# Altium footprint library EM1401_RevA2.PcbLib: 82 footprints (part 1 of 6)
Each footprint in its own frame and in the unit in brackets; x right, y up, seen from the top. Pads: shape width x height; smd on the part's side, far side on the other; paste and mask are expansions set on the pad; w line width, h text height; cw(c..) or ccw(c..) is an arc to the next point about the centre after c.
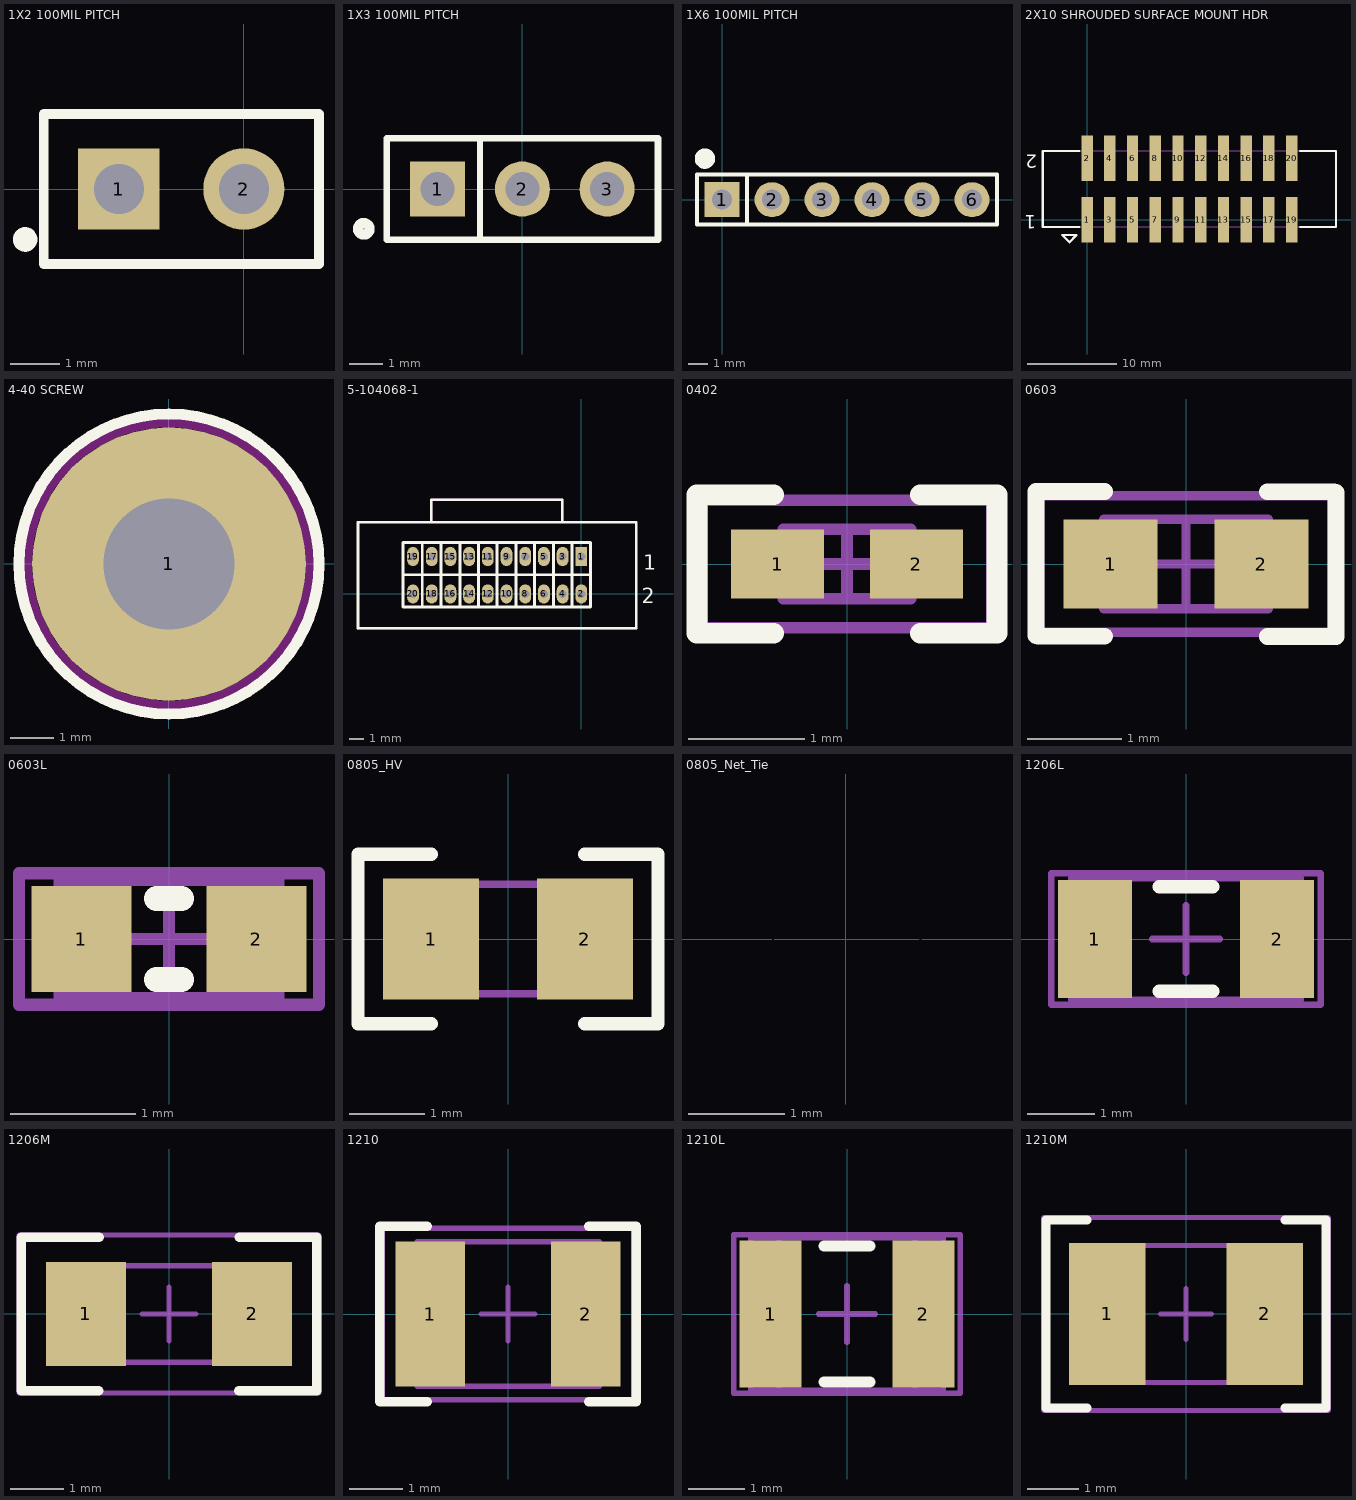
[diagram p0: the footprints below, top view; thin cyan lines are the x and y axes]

## 1X2 100MIL PITCH [mm] "100 mil 1x2 header, 230 mil above insulator"
height 8.382
pads (2):
  rect 1.65x1.65 hole 1.016: 1(-2.54,0)
  round 1.65 hole 1.016: 2(0,0)
Top Overlay:
  circle w0.25: c-4.441,-1.025 r0.125
  lines w0.2: -4.064,-1.524 1.525,-1.524 1.525,1.524 -4.064,1.524 -4.064,-1.524
Mechanical 5:
  text ".designator" at -0.875,-0.538 h1.02

## 1X3 100MIL PITCH [mm] "100 mil 1x3 header, 230 mil above insulator"
height 8.382
pads (3):
  rect 1.65x1.65 hole 1.016: 1(-2.54,0)
  round 1.65 hole 1.016: 2(0,0) 3(2.54,0)
Top Overlay:
  circle w0.305: c-4.754,-1.194 r0.173
  lines w0.178: -1.27,-1.524 -1.27,1.46
  lines w0.2: -4.064,-1.524 4.064,-1.524 4.064,1.524 -4.064,1.524 -4.064,-1.524
Mechanical 5:
  text ".designator" at -0.875,-0.538 h1.02
3D body: height 8.38, standoff -2.54, extent -3.81,-1.27 3.81,1.27

## 1X6 100MIL PITCH [mil] "CONN HEADER VERT SGL 6POS"
height 570
pads (6):
  rect 70x70 hole 40: 1(0,0)
  round 70 hole 40: 2(100,0) 3(200,0) 4(300,0) 5(400,0) 6(500,0)
Top Overlay:
  circle w20: c-34,82 r10.44
  lines w7.87: 50.2,-50 50.2,50 ; -50,-50 -50,50 550,50 550,-50 -50,-50
Mechanical 5:
  text ".Designator" at -0.94,-0.32 h40
Mechanical 13:
  lines w3.94: -50,-50 -50,50 550,50 550,-50 -50,-50
Mechanical 15:
  lines w3.94: -19.68,0 19.68,0 ; 0,-19.68 0,19.68 ; -50,-50 -50,50 550,50 550,-50 -50,-50
3D body: height 68.9, standoff 0, extent -50,-50 550,50

## 2X10 SHROUDED SURFACE MOUNT HDR [mil] "2X10 Shrouded Surface Mount HDR"
height 390.16
pads (20):
  rect 50x200 smd: 1(0,0) 2(0,270) 3(100,0) 4(100,270) 5(200,0) 6(200,270) 7(300,0) 8(300,270) 9(400,0) 10(400,270) 11(500,0) 12(500,270) 13(600,0) 14(600,270) 15(700,0) 16(700,270) 17(800,0) 18(800,270) 19(900,0) 20(900,270)
Top Overlay:
  lines w9.84: -109.24,-67.54 -46.24,-67.54 -77.74,-99.04 -109.24,-67.54
  lines w10: -35,-32.11 -195.85,-32.11 -195.85,302.54 -35,302.54 ; 937.11,-32.11 1095.49,-32.11 1095.49,302.54 937.46,302.54
  text "2" at -220,285 h60
  text "1" at -225,20 h60
Mechanical 15:
  lines w3.94: -195.85,-32.11 1095.49,-32.11 1095.49,302.54 -195.85,302.54 -195.85,-32.11
3D body: height 68.9, standoff 0, extent -194.67,-32.11 1095.49,302.54
3D body: height 349.4, standoff -130.6, extent -200,-46.5 1100,326.5

## 4-40 SCREW [mil] "Hole and Pad for 4-40 screw mount"
pads (1):
  round 250 hole 120: 1(0,0)
Top Overlay:
  circle w10: c0,0 r137
Keep-Out Layer:
  circle w10: c-0.36,0 r129.66

## 5-104068-1 [mm] "AMP 20PIN VERT HEADER ASSY"
height 8.89
pads (20):
  rect 0.8x1.3 hole 0.559: 1(0,2.54)
  oval 0.8x1.3 hole 0.559: 2(0,0) 3(-1.27,2.54) 4(-1.27,0) 5(-2.54,2.54) 6(-2.54,0) 7(-3.81,2.54) 8(-3.81,0) 9(-5.08,2.54) 10(-5.08,0) 11(-6.35,2.54) 12(-6.35,0) 13(-7.62,2.54) 14(-7.62,0) 15(-8.89,2.54) 16(-8.89,0) 17(-10.16,2.54) 18(-10.16,0) 19(-11.43,2.54) 20(-11.43,0)
Top Overlay:
  lines w0.178: -10.18,4.876 -10.18,6.4 -1.29,6.4 -1.29,4.876 ; -15.164,-2.337 3.734,-2.337 3.734,4.877 -15.164,4.877 -15.164,-2.337
  lines w0.2: -12.1,1.3 -10.8,1.3 -9.5,1.3 -8.2,1.3 ; -9.5,-0.9 -8.25,-0.9 -8.25,3.5 -9.5,3.5 ; -8.275,-0.9 -6.975,-0.9 -6.975,3.5 -8.275,3.5 ; -8.275,1.3 -6.975,1.3 ; -7.025,-0.9 -5.725,-0.9 -5.725,3.5 -7.025,3.5 ; -7.025,1.3 -5.725,1.3 ; -5.75,-0.9 -4.45,-0.9 -4.45,3.5 -5.75,3.5 ; -5.75,1.3 -4.45,1.3 ; -4.475,-0.9 -3.175,-0.9 -3.175,3.5 -4.475,3.5 ; -4.475,1.3 -3.175,1.3 ; -3.2,-0.9 -1.9,-0.9 -1.9,3.5 -3.2,3.5 ; -3.2,1.3 -1.9,1.3 ; -1.925,-0.9 -0.625,-0.9 -0.625,3.5 -1.925,3.5 ; -1.925,1.3 -0.625,1.3 ; -0.675,-0.9 0.625,-0.9 0.625,3.5 -0.675,3.5 ; -0.675,1.3 0.625,1.3 ; -12.1,3.5 -10.8,3.5 ; -12.1,3.5 -12.1,3.5 ; -12.1,3.5 -12.1,-0.9 -10.8,-0.9 ; -10.8,-0.9 -10.8,3.5 ; -10.8,-0.9 -9.525,-0.9 -9.525,3.5 -10.8,3.5
  text "1" at 4.191,1.651 h1.02
  text "2" at 4.115,-0.635 h1.02
Mechanical 5:
  text ".Designator" at -6.94,1.02 h1.02
Mechanical 15:
  lines w0.127: -10.18,4.876 -10.18,6.4 -1.29,6.4 -1.29,4.876 ; 3.734,-2.337 3.734,4.877 -15.164,4.877 -15.164,-2.337 3.759,-2.337
3D body: height 11.43, standoff -1.02, extent -15.164,-2.337 3.734,6.401

## 0402 [mm] "0402 from SM-752 data"
height 0.6
pads (2):
  rect 0.8x0.6 smd: 1(-0.6,0) 2(0.6,0)
Top Overlay:
  lines w0.178: -0.635,-0.597 -1.295,-0.597 -1.295,0.597 -0.635,0.597 ; 0.635,-0.597 1.295,-0.597 1.295,0.597 0.635,0.597
Mechanical 5:
  text ".Designator" at -1.117,-0.305 h0.61
Mechanical 13:
  lines w0.1: -0.35,-0.3 -0.35,0.3 ; 0.35,-0.3 0.35,0.3 ; -0.55,-0.3 -0.55,0.3 0.55,0.3 0.55,-0.3 -0.55,-0.3
Mechanical 15:
  lines w0.1: -0.3,0 0.3,0 ; 0,-0.3 0,0.3 ; -1.25,-0.55 -1.25,0.55 1.25,0.55 1.25,-0.55 -1.25,-0.55
3D body: height 0.6, standoff 0, extent -0.549,-0.299 -0.351,0.299
3D body: height 0.6, standoff 0, extent -0.349,-0.299 0.349,0.299
3D body: height 0.6, standoff 0, extent 0.351,-0.299 0.549,0.299

## 0603 [mm] "0603 from SM-752 data"
height 0.85
pads (2):
  rect 1x0.95 smd: 1(-0.8,0) 2(0.8,0)
Top Overlay:
  lines w0.178: -1.593,-0.762 -1.593,0.769 -0.864,0.769 ; -1.575,-0.767 -0.864,-0.767 ; 0.864,-0.769 1.593,-0.769 1.593,0.762 ; 0.864,0.767 1.575,0.767
Mechanical 5:
  text ".Designator" at -1.397,-0.381 h0.76
Mechanical 13:
  lines w0.1: -0.55,-0.475 -0.55,0.475 ; 0.55,-0.475 0.55,0.475 ; -0.875,-0.475 0.875,-0.475 0.875,0.475 -0.875,0.475 -0.875,-0.475
Mechanical 15:
  lines w0.1: -0.475,0 0.475,0 ; 0,-0.475 0,0.475 ; -1.55,-0.725 -1.55,0.725 1.55,0.725 1.55,-0.725 -1.55,-0.725
3D body: height 0.85, standoff 0, extent -0.549,-0.474 0.549,0.474
3D body: height 0.85, standoff 0, extent -0.874,-0.474 -0.551,0.474
3D body: height 0.85, standoff 0, extent 0.551,-0.474 0.874,0.474

## 0603L [mm] "0603 from SM-752 data"
height 0.85
pads (2):
  rect 0.8x0.85 smd: 1(-0.7,0) 2(0.7,0)
Top Overlay:
  lines w0.2: -0.1,-0.325 0.1,-0.325 ; -0.1,0.325 0.1,0.325
Mechanical 5:
  text ".Designator" at -1.164,-0.317 h0.64
Mechanical 13:
  lines w0.1: -0.55,-0.475 -0.55,0.475 ; 0.55,-0.475 0.55,0.475 ; -0.875,-0.475 0.875,-0.475 0.875,0.475 -0.875,0.475 -0.875,-0.475
Mechanical 15:
  lines w0.1: -0.475,0 0.475,0 ; 0,-0.475 0,0.475 ; -1.2,-0.525 1.2,-0.525 1.2,0.525 -1.2,0.525 -1.2,-0.525
3D body: height 0.85, standoff 0, extent 0.551,-0.474 0.874,0.474
3D body: height 0.85, standoff 0, extent -0.549,-0.474 0.549,0.474
3D body: height 0.85, standoff 0, extent -0.874,-0.474 -0.551,0.474

## 0805_HV [mil] "0805 with 30mil clearance between pads"
height 43.31
pads (2):
  rect 50x63 smd: 1(-40,0) 2(40,0)
Top Overlay:
  lines w7: -40,-44 -78,-44 -78,0 -78,44 -40,44 ; 40,-44 78,-44 78,0 78,44 40,44
Mechanical 5:
  text ".Designator" at -73.31,-19.99 h40
Mechanical 13:
  lines w3.94: -25.59,-28.54 -25.59,28.54 ; 25.59,-28.54 25.59,28.54 ; -43.31,-28.54 43.31,-28.54 43.31,28.54 -43.31,28.54 -43.31,-28.54
3D body: height 43.31, standoff 0, extent -25.57,-28.52 25.57,28.52
3D body: height 43.31, standoff 0, extent 25.61,-28.52 43.29,28.52
3D body: height 43.31, standoff 0, extent -43.29,-28.52 -25.61,28.52

## 0805_Net_Tie [mm]
pads (2):
  rect 1.55x1.6 on Mid7 paste+0 mask+0: 1(-0.75,0)
  rect 1.55x1.6 on Mid7: 2(0.775,0)

## 1206L [mm] "1206 from SM-752 data"
height 1.35
pads (2):
  rect 1.1x1.75 smd: 1(-1.35,0) 2(1.35,0)
Top Overlay:
  lines w0.2: -0.4,-0.775 0.4,-0.775 ; -0.4,0.775 0.4,0.775
Mechanical 5:
  text ".Designator" at -1.524,-0.508 h1.02
Mechanical 13:
  lines w0.1: -1.2,-0.9 -1.2,0.9 ; 1.2,-0.9 1.2,0.9 ; -1.7,-0.9 1.7,-0.9 1.7,0.9 -1.7,0.9 -1.7,-0.9
Mechanical 15:
  lines w0.1: -0.5,0 0.5,0 ; 0,-0.5 0,0.5 ; -2,-0.975 2,-0.975 2,0.975 -2,0.975 -2,-0.975
3D body: height 1.35, standoff 0, extent 1.201,-0.899 1.699,0.899
3D body: height 1.35, standoff 0, extent -1.199,-0.899 1.199,0.899
3D body: height 1.35, standoff 0, extent -1.699,-0.899 -1.201,0.899

## 1206M [mm] "1206 from SM-752 data"
height 1.35
pads (2):
  rect 1.5x1.95 smd: 1(-1.55,0) 2(1.55,0)
Top Overlay:
  lines w0.178: -2.758,-1.43 -2.753,-1.435 ; -1.313,-1.435 -2.758,-1.435 -2.758,1.435 -1.303,1.435 ; 1.306,-1.435 2.761,-1.435 2.761,1.435 1.316,1.435 ; 2.756,1.435 2.761,1.43
Mechanical 5:
  text ".designator" at -1.844,-0.584 h1.02
Mechanical 13:
  lines w0.1: -1.7,-0.9 -1.7,0.9 1.7,0.9 1.7,-0.9 -1.7,-0.9
Mechanical 15:
  lines w0.1: -0.5,0 0.5,0 ; 0,-0.5 0,0.5 ; -2.8,-1.475 -2.8,1.475 2.8,1.475 2.8,-1.475 -2.8,-1.475
3D body: height 1.35, standoff 0, extent -1.7,-0.9 1.7,0.9

## 1210 [mm] "1210 from SM-752 data"
height 1.35
pads (2):
  rect 1.3x2.7 smd: 1(-1.45,0) 2(1.45,0)
Top Overlay:
  lines w0.178: -1.511,-1.639 -2.39,-1.639 -2.39,1.639 -1.511,1.639 ; 1.511,-1.639 2.39,-1.639 2.39,1.639 1.511,1.639
Mechanical 5:
  text ".Designator" at -1.524,-0.508 h1.02
Mechanical 13:
  lines w0.1: -1.2,-1.35 -1.2,1.35 ; 1.2,-1.35 1.2,1.35 ; -1.7,-1.35 1.7,-1.35 1.7,1.35 -1.7,1.35 -1.7,-1.35
Mechanical 15:
  lines w0.1: -0.5,0 0.5,0 ; 0,-0.5 0,0.5 ; -2.35,-1.6 2.35,-1.6 2.35,1.6 -2.35,1.6 -2.35,-1.6
3D body: height 1.35, standoff 0, extent 1.201,-1.349 1.699,1.349
3D body: height 1.35, standoff 0, extent -1.199,-1.349 1.199,1.349
3D body: height 1.35, standoff 0, extent -1.699,-1.349 -1.201,1.349

## 1210L [mm] "1210 from SM-752 data"
height 1.35
pads (2):
  rect 1.1x2.6 smd: 1(-1.35,0) 2(1.35,0)
Top Overlay:
  lines w0.2: -0.4,-1.2 0.4,-1.2 ; -0.4,1.2 0.4,1.2
Mechanical 5:
  text ".Designator" at -1.524,-0.508 h1.02
Mechanical 13:
  lines w0.1: -1.2,-1.35 -1.2,1.35 ; 1.2,-1.35 1.2,1.35 ; -1.7,-1.35 -1.7,1.35 1.7,1.35 1.7,-1.35 -1.7,-1.35
Mechanical 15:
  lines w0.1: -0.5,0 0.5,0 ; 0,-0.5 0,0.5 ; -2,-1.4 -2,1.4 2,1.4 2,-1.4 -2,-1.4
3D body: height 1.35, standoff 0, extent -1.699,-1.349 -1.201,1.349
3D body: height 1.35, standoff 0, extent -1.199,-1.349 1.199,1.349
3D body: height 1.35, standoff 0, extent 1.201,-1.349 1.699,1.349

## 1210M [mm] "1210 from SM-752 data"
height 1.35
pads (2):
  rect 1.5x2.8 smd: 1(-1.55,0) 2(1.55,0)
Top Overlay:
  lines w0.178: -1.95,-1.85 -2.75,-1.85 -2.75,1.85 -1.95,1.85 ; 1.95,-1.85 2.75,-1.85 2.75,1.85 1.95,1.85
Mechanical 5:
  text ".Designator" at -1.524,-0.508 h1.02
Mechanical 13:
  lines w0.1: -1.2,-1.35 -1.2,1.35 ; 1.2,-1.35 1.2,1.35 ; -1.7,-1.35 -1.7,1.35 1.7,1.35 1.7,-1.35 -1.7,-1.35
Mechanical 15:
  lines w0.1: -0.5,0 0.5,0 ; 0,-0.5 0,0.5 ; -2.8,-1.9 2.8,-1.9 2.8,1.9 -2.8,1.9 -2.8,-1.9
3D body: height 1.35, standoff 0, extent 1.201,-1.349 1.699,1.349
3D body: height 1.35, standoff 0, extent -1.199,-1.349 1.199,1.349
3D body: height 1.35, standoff 0, extent -1.699,-1.349 -1.201,1.349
